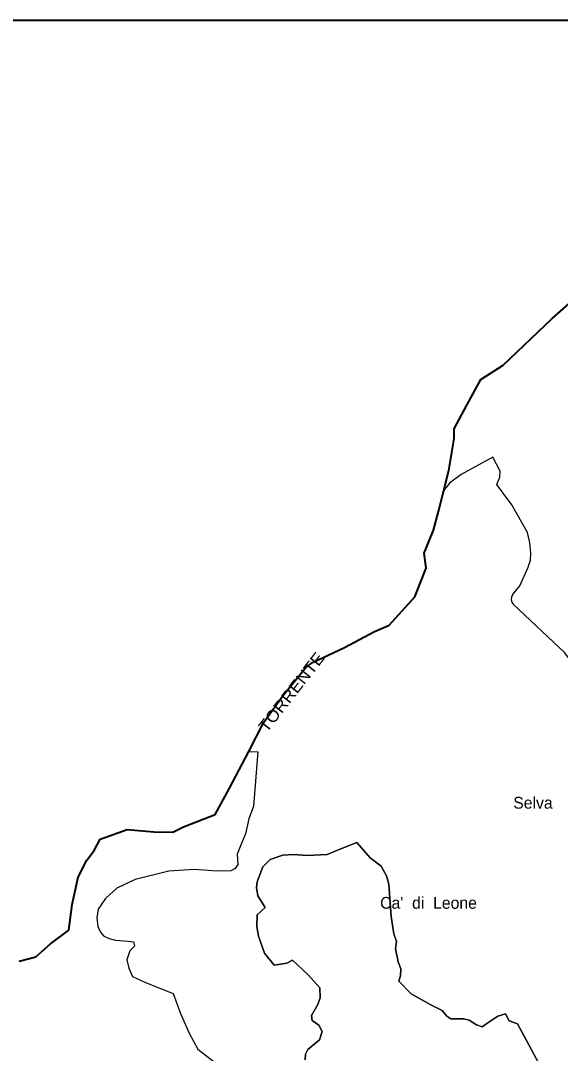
# Model space of a CAD drawing. Extents: x 645880 to 658994, y 884400 to 894744.
# Drawn here: x 655242 to 656021, y 893255 to 894744 of the extents above; entities that cross this region are included whole.
import ezdxf
from ezdxf.enums import TextEntityAlignment as Align

# ---------------------------------------------------------------- set-up
doc = ezdxf.new("R2010")
doc.units = 0
doc.header["$LTSCALE"] = 10
for name, color, linetype, lineweight in [('16', 7, 'Continuous', 25), ('18', 7, 'Continuous', 25), ('59', 7, 'Continuous', 40), ('62', 7, 'Continuous', 35)]:
    doc.layers.add(name, color=color, linetype=linetype, lineweight=lineweight)
doc.layers.add('60', color=7, linetype='Continuous')

msp = doc.modelspace()

# ---------------------------------------------------------------- linework, layer by layer
at = {"layer": '16'}
for points in [[(655978, 893976.34), (655976.52, 893991.12), (655973.22, 894006.2), (655950.75, 894045.98), (655938.16, 894062.77), (655929.09, 894075.33), (655933.22, 894085.75), (655933.95, 894094.46), (655923.34, 894114.83), (655877.83, 894089.86), (655860.84, 894077.25), (655852.29, 894065.91), (655844.73, 894036.26), (655837.59, 894009.32), (655824.1, 893976.23), (655827.28, 893954.68), (655810.95, 893913.51), (655773.67, 893872.72), (655751.45, 893862.72), (655709.41, 893840.4), (655663.4, 893818.86), (655653.09, 893811.16), (655619.77, 893770.37), (655592.8, 893732.66), (655571.4, 893690.37), (655584.52, 893690.03), (655578, 893611.65), (655571.49, 893593.18), (655566.4, 893571.73), (655560.46, 893556.77), (655554.59, 893542.68), (655555.53, 893527.46)], [(655974.38, 893956.02), (655977.62, 893966.44), (655978, 893976.34)], [(655951.76, 893916.04), (655962.05, 893929.16), (655974.38, 893956.02)], [(656130.02, 893649.21), (656136.6, 893658.13), (656144.57, 893678.46), (656147.47, 893693.7), (656137.32, 893703.13), (656130.8, 893710.39), (656127.9, 893715.47), (656125.73, 893722.73), (656122.1, 893726.36), (656109.74, 893734.54), (656106.88, 893745.23), (656101.8, 893755.39), (656094.55, 893767), (656094.55, 893777.88), (656091.65, 893782.96), (656053.77, 893818.36), (656044.01, 893817.61), (656036.12, 893820.24), (656027.23, 893832.73), (655952.79, 893902.58)], [(655594.74, 893465.4), (655584.23, 893482.31), (655582.35, 893494.54), (655583.48, 893502.6), (655591.74, 893524.03), (655602.26, 893534.55), (655620.29, 893540.94), (655635.99, 893541.98), (655655.57, 893540.53), (655684.52, 893542.07), (655701.8, 893549.21), (655727.34, 893559.36), (655746.32, 893537.17), (655762.29, 893525.38), (655770.02, 893511.21), (655773.29, 893499.42), (655776.54, 893452.71), (655780.3, 893427.81), (655784.27, 893416.62), (655783.05, 893406.24)], [(655555.53, 893527.46), (655551.78, 893522.01), (655545.44, 893518.5), (655526.19, 893517.79), (655492.63, 893520.14), (655455.78, 893517.79), (655407.43, 893505.81), (655380.92, 893493.37), (655364.72, 893478.57), (655354.24, 893463.4)], [(655354.24, 893463.4), (655352.29, 893450.86), (655353.51, 893438)], [(655652.59, 893245.87), (655652.9, 893254.21), (655656.27, 893260.95), (655673.25, 893274.81), (655677.27, 893286.81), (655672.13, 893296.24), (655662.77, 893302.78), (655661.99, 893309.77), (655670.76, 893325.78), (655674.38, 893335.22), (655673.89, 893349.59), (655656.98, 893368.6), (655634.51, 893389.65), (655626.13, 893385.49), (655607.9, 893382.51), (655593.91, 893399.81), (655585.33, 893424.33), (655583.16, 893438.12), (655583.47, 893454.87), (655594.74, 893465.4)], [(655353.51, 893438), (655357.45, 893430.19), (655361.91, 893424.55)], [(655361.91, 893424.55), (655369.89, 893420.79), (655379.05, 893418.68), (655397.59, 893417.04), (655404.99, 893416.23), (655406.27, 893409.99), (655399.93, 893402.94), (655395.24, 893390.03), (655398.29, 893378.28), (655403.54, 893366.15), (655422.38, 893357.44), (655462.26, 893341.48), (655473.06, 893312.72), (655485.39, 893284.42), (655497.71, 893261.19), (655523.09, 893241.6)], [(655783.05, 893406.24), (655786.64, 893387.47), (655790.41, 893377.36), (655790.21, 893367.24), (655787.88, 893359.34), (655805.28, 893341.26), (655832.82, 893325.8), (655850.26, 893317.07), (655857.01, 893309.16), (655862.81, 893304.93), (655872, 893304.93), (655881.18, 893304.93), (655888.92, 893303.06), (655899.55, 893296.49), (655907.77, 893293.68), (655915.99, 893299.31), (655930.49, 893309.16), (655941.61, 893312.44), (655946.85, 893302.46), (655958.71, 893297.96), (655964.9, 893286.46), (655989.13, 893241.94)]]:
    msp.add_lwpolyline(points, dxfattribs=at)
msp.add_arc((655959.63, 893909.87), 10, 141.8889, 226.81079, dxfattribs=at)
at = {"layer": '18'}
for points in [[(655978, 893976.34), (655976.52, 893991.12), (655973.22, 894006.2), (655950.75, 894045.98), (655938.16, 894062.77), (655929.09, 894075.33), (655933.22, 894085.75), (655933.95, 894094.46), (655923.34, 894114.83), (655877.83, 894089.86), (655860.84, 894077.25), (655852.29, 894065.91), (655859.83, 894095.54), (655867.77, 894141.72), (655867.77, 894155.57), (655885.99, 894189.66), (655905.82, 894226.6), (655938.35, 894247.38), (656008.95, 894314.33), (656032.75, 894335.88), (656057.34, 894351.27), (656108.11, 894357.43)], [(655974.38, 893956.02), (655977.62, 893966.44), (655978, 893976.34)], [(655951.76, 893916.04), (655962.05, 893929.16), (655974.38, 893956.02)], [(656130.02, 893649.21), (656136.6, 893658.13), (656144.57, 893678.46), (656147.47, 893693.7), (656137.32, 893703.13), (656130.8, 893710.39), (656127.9, 893715.47), (656125.73, 893722.73), (656122.1, 893726.36), (656109.74, 893734.54), (656106.88, 893745.23), (656101.8, 893755.39), (656094.55, 893767), (656094.55, 893777.88), (656091.65, 893782.96), (656053.77, 893818.36), (656044.01, 893817.61), (656036.12, 893820.24), (656027.23, 893832.73), (655952.79, 893902.58)], [(655240.3, 893388.47), (655264.1, 893394.63), (655285.52, 893413.1), (655311.7, 893433.11), (655316.46, 893470.05), (655325.18, 893509.3), (655337.88, 893533.92), (655348.49, 893548), (655357.22, 893564.16), (655396.09, 893578.01), (655434.17, 893574.93), (655461.93, 893574.16), (655477, 893581.86), (655523.02, 893599.56), (655542.85, 893636.5), (655571.41, 893690.37), (655584.52, 893690.03), (655578, 893611.65), (655571.49, 893593.18), (655566.4, 893571.73), (655560.46, 893556.77), (655554.59, 893542.68), (655555.53, 893527.46)], [(655790.41, 893377.36), (655786.64, 893387.47), (655783.05, 893406.24), (655784.27, 893416.62), (655780.3, 893427.81), (655776.54, 893452.71), (655773.29, 893499.42), (655770.02, 893511.21), (655762.29, 893525.38), (655746.32, 893537.17), (655727.34, 893559.36), (655701.8, 893549.21), (655684.52, 893542.07), (655655.57, 893540.53), (655635.99, 893541.98), (655620.29, 893540.94), (655602.26, 893534.55), (655591.74, 893524.03), (655583.48, 893502.6), (655582.35, 893494.54)], [(655555.53, 893527.46), (655551.78, 893522.01), (655545.44, 893518.5), (655526.19, 893517.79), (655492.63, 893520.14), (655455.78, 893517.79), (655407.43, 893505.81), (655380.92, 893493.37), (655364.72, 893478.57), (655354.24, 893463.4)], [(655582.35, 893494.54), (655584.23, 893482.31), (655594.74, 893465.4), (655583.47, 893454.87), (655583.16, 893438.12), (655585.33, 893424.33), (655593.91, 893399.81), (655607.9, 893382.51), (655626.13, 893385.49), (655634.51, 893389.65), (655656.98, 893368.6), (655673.89, 893349.59), (655674.38, 893335.22), (655670.76, 893325.78), (655661.99, 893309.77), (655662.77, 893302.78), (655672.13, 893296.24), (655677.27, 893286.81), (655673.25, 893274.81), (655656.27, 893260.95)], [(655354.24, 893463.4), (655352.29, 893450.86), (655353.51, 893438)], [(655353.51, 893438), (655357.45, 893430.19), (655361.91, 893424.55)], [(655361.91, 893424.55), (655369.89, 893420.79), (655379.05, 893418.68), (655397.59, 893417.04), (655404.99, 893416.23), (655406.27, 893409.99), (655399.93, 893402.94), (655395.24, 893390.03), (655398.29, 893378.28), (655403.54, 893366.15), (655422.38, 893357.44), (655462.26, 893341.48), (655473.06, 893312.72), (655485.39, 893284.42), (655497.71, 893261.19), (655523.09, 893241.6)], [(655989.13, 893241.94), (655964.9, 893286.46), (655958.71, 893297.96), (655946.85, 893302.46), (655941.61, 893312.44), (655930.49, 893309.16), (655915.99, 893299.31), (655907.77, 893293.68), (655899.55, 893296.49), (655888.92, 893303.06), (655881.18, 893304.93), (655872, 893304.93), (655862.81, 893304.93), (655857.01, 893309.16), (655850.26, 893317.07), (655832.82, 893325.8), (655805.28, 893341.26), (655787.88, 893359.34), (655790.21, 893367.24), (655790.41, 893377.36)], [(655656.27, 893260.95), (655652.9, 893254.21), (655652.59, 893245.87)]]:
    msp.add_lwpolyline(points, dxfattribs=at)
msp.add_arc((655959.63, 893909.87), 10, 141.8889, 226.81079, dxfattribs=at)
at = {"layer": '59'}
for points in [[(655810.95, 893913.51), (655827.28, 893954.68), (655824.1, 893976.23), (655837.59, 894009.32), (655844.73, 894036.26), (655859.8, 894095.51), (655867.74, 894141.69), (655867.74, 894155.54), (655885.96, 894189.63), (655905.79, 894226.57), (655938.32, 894247.35), (656008.92, 894314.3), (656032.72, 894335.85)], [(655240.27, 893388.44), (655264.07, 893394.6), (655285.49, 893413.07), (655311.67, 893433.08), (655316.43, 893470.02), (655325.15, 893509.27), (655337.85, 893533.89), (655348.46, 893547.97), (655357.19, 893564.13), (655396.06, 893577.98), (655434.14, 893574.9), (655461.9, 893574.13), (655476.97, 893581.83), (655522.99, 893599.53), (655542.82, 893636.47), (655571.38, 893690.34), (655592.8, 893732.66), (655619.77, 893770.37), (655653.09, 893811.16), (655663.4, 893818.86), (655709.41, 893840.4), (655751.45, 893862.72), (655773.67, 893872.72), (655810.95, 893913.51)]]:
    msp.add_lwpolyline(points, dxfattribs=at)
at = {"layer": '62', "lineweight": 40}
msp.add_lwpolyline([(650022.35, 889003.81), (658994.16, 889003.81), (658994.16, 894743.81), (650022.35, 894743.81)], close=True, dxfattribs=at)
msp.add_lwpolyline([(650022.35, 889003.81), (658994.16, 889003.81), (658994.16, 894743.81), (650022.35, 894743.81)], close=True, dxfattribs=at)

# ---------------------------------------------------------------- texts
at = {"layer": '60', "width": 1.1}
msp.add_text('TORRENTE', height=17, rotation=52.072, dxfattribs=at).set_placement((655639.56, 893770.95), align=Align.CENTER)
at = {"layer": '60'}
for s, p in [('Selva', (655981.17, 893608.06)), ("Ca'  di  Leone", (655830.55, 893463.8))]:
    msp.add_text(s, height=17, dxfattribs=at).set_placement(p, align=Align.CENTER)

doc.saveas('drawing.dxf')
